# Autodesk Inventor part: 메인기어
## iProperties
Company: 한국ATC센터
Created: 2014-12
Part Number: 메인기어
Document SubType Name: Modeling
Designer: KYOUNG IL JANG
Density: 1 g/cm^3
Mass: 43.883 g
Surface Area: 122.661 cm^2
Volume: 43.883 cm^3
Author: KYOUNG IL JANG
